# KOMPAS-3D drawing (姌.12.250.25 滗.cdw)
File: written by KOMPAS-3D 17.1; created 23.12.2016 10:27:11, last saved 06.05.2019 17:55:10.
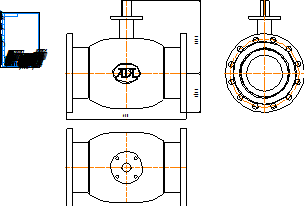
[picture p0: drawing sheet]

Sheet 1: A4, portrait

Title block, sheet 1: name: КШ.12.250.25 фф; material: Внимание! Данный продукт является объектом авторского права ООО «Торговый Дом АДЛ». / Запрещается изменение, копирование, распространение / (в том числе путем копирования на другие сайты и ресурсы в Интернете) / или любое иное использование информации и объектов без предварительного / согласия правообладателя (ООО «Торговый Дом АДЛ»).; sheets: 1; organisation: ООО "Торговый дом АДЛ"; sheet format: A4; stored path: C:\Users\tra\Desktop\2д чертежи\Шаровые краны БИВАЛ\КШ_Бивал_серия_11_12\KOMPAS_2D\КШ.12.250.25 фф.cdw

Views: Вид 1, Проекционный вид 2, Проекционный вид 3
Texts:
  Klimkovich
  ADL
Dimensions and other numbers on the sheet: 650; 389,5; 212,5; 1:1; 1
